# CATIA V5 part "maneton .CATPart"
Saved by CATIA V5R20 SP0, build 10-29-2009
Part number: 6
Bounding box of the stored display mesh (mm): x -12 to 12, y -11.818 to 11.818, z 0 to 50
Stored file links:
  C:\Users\halimelbaba\Documents\cmv\projet\maneton .CATPart
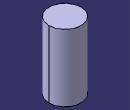
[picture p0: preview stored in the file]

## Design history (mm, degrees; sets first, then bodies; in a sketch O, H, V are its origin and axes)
Body1 (main body)
  Sketch1 on xy-plane, origin (0, 0, 0), H (1, 0, 0), V (0, 1, 0)
    circle A1 centre (0, 0) radius 12
    radius A1 = 12
  Pad1: profile Sketch1, direction (0, 0, 1), length 50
